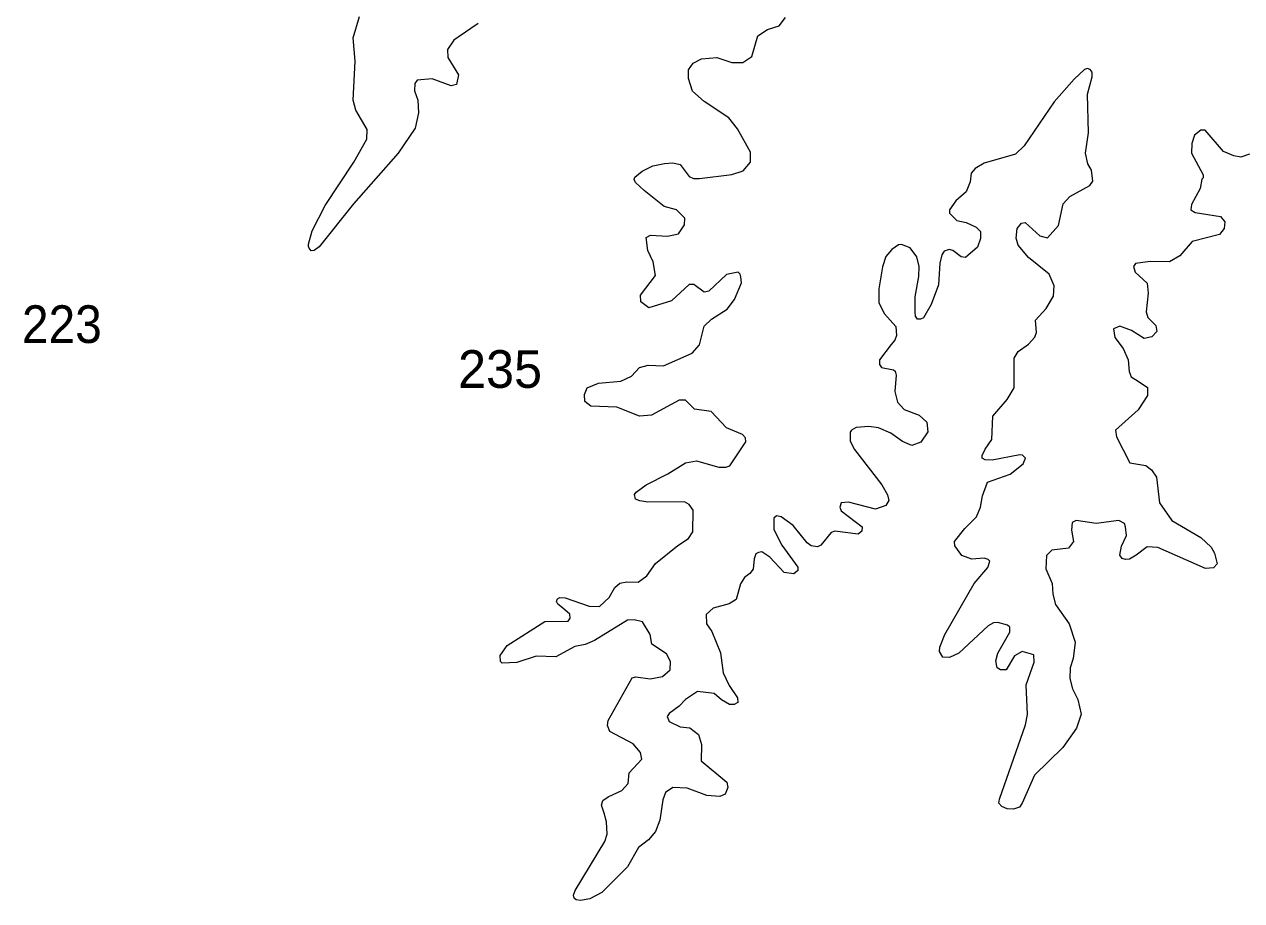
# Model space of a CAD drawing. Extents: x 499.9 to 555.3, y 9281.5 to 9336.8.
# Drawn here: x 512.89 to 518.06, y 9302.13 to 9305.85 of the extents above; entities that cross this region are included whole.
import ezdxf

# ---------------------------------------------------------------- set-up
doc = ezdxf.new("R2010")
doc.units = 0
doc.header["$LTSCALE"] = 0.064
doc.layers.add('2', color=7, linetype='Continuous', lineweight=13)
doc.layers.add('21', color=7, linetype='Continuous')

msp = doc.modelspace()

# ---------------------------------------------------------------- linework, layer by layer
at = {"layer": '2'}
for points in [[(514.8193, 9305.8589), (514.7874, 9305.8369), (514.7156, 9305.7877), (514.6882, 9305.7478), (514.69, 9305.7137), (514.7351, 9305.6398), (514.7267, 9305.5994), (514.7046, 9305.5935), (514.624, 9305.6231), (514.5599, 9305.6174), (514.5495, 9305.6034), (514.5478, 9305.5725), (514.562, 9305.5326), (514.5651, 9305.4786), (514.5516, 9305.4136), (514.4788, 9305.3076), (514.2894, 9305.0927), (514.1435, 9304.9091), (514.1218, 9304.8934), (514.109, 9304.8929), (514.1005, 9304.9034), (514.0978, 9304.9113), (514.0975, 9304.9206), (514.1143, 9304.9777), (514.1695, 9305.0845), (514.2911, 9305.2694), (514.3454, 9305.3672), (514.3469, 9305.4084), (514.2989, 9305.4895), (514.2885, 9305.5326), (514.2962, 9305.6981), (514.2884, 9305.7978), (514.3142, 9305.8875)], [(515.9078, 9304.6861), (515.9369, 9304.7561), (515.9342, 9304.7814), (515.9307, 9304.7937), (515.9224, 9304.8017), (515.873, 9304.7918), (515.798, 9304.7204), (515.779, 9304.7167), (515.735, 9304.7492), (515.7143, 9304.7495), (515.6404, 9304.6795), (515.5433, 9304.6499), (515.5099, 9304.676), (515.5086, 9304.7048), (515.5723, 9304.787), (515.5615, 9304.8451), (515.5393, 9304.8936), (515.5319, 9304.9484), (515.5504, 9304.9597), (515.6221, 9304.9551), (515.6696, 9304.9648), (515.6947, 9305.0036), (515.6966, 9305.0306), (515.6615, 9305.0668), (515.6088, 9305.0812), (515.5235, 9305.1493), (515.487, 9305.183), (515.4812, 9305.196), (515.4839, 9305.2058), (515.5155, 9305.2302), (515.561, 9305.2537), (515.6101, 9305.2636), (515.6454, 9305.2662), (515.6771, 9305.2589), (515.7146, 9305.2083), (515.7326, 9305.2), (515.7581, 9305.2001), (515.8966, 9305.2162), (515.9435, 9305.232), (515.9753, 9305.2693), (515.9752, 9305.3111), (515.9201, 9305.411), (515.883, 9305.4577), (515.778, 9305.5267), (515.729, 9305.571), (515.7114, 9305.625), (515.7118, 9305.6619), (515.7311, 9305.6904), (515.7667, 9305.7083), (515.832, 9305.714), (515.8959, 9305.6919), (515.943, 9305.6932), (515.9802, 9305.7178), (516.006, 9305.8062), (516.0481, 9305.833), (516.0975, 9305.8478), (516.1235, 9305.8836)], [(516.9596, 9304.0121), (516.959, 9304.0232), (516.9719, 9304.0493), (517, 9304.0907), (517.0042, 9304.1899), (517.0655, 9304.261), (517.0956, 9304.3104), (517.0951, 9304.4359), (517.112, 9304.4645), (517.1562, 9304.4966), (517.182, 9304.5258), (517.1895, 9304.5459), (517.1856, 9304.5973), (517.231, 9304.6478), (517.2615, 9304.7005), (517.2643, 9304.7432), (517.2434, 9304.7938), (517.1564, 9304.8642), (517.1123, 9304.9162), (517.104, 9304.9465), (517.1071, 9304.9875), (517.1257, 9305.0099), (517.142, 9305.0133), (517.2037, 9304.9556), (517.2371, 9304.9481), (517.2837, 9305.0005), (517.3025, 9305.0916), (517.3316, 9305.1234), (517.4157, 9305.1704), (517.4295, 9305.1883), (517.4239, 9305.2352), (517.408, 9305.2622), (517.3983, 9305.3073), (517.411, 9305.3934), (517.4063, 9305.5581), (517.4263, 9305.632), (517.4264, 9305.6514), (517.418, 9305.6623), (517.4063, 9305.6671), (517.3937, 9305.6628), (517.35, 9305.6213), (517.2651, 9305.5252), (517.1377, 9305.3391), (517.1004, 9305.3032), (516.967, 9305.2642), (516.9295, 9305.2418), (516.9123, 9305.2218), (516.908, 9305.1856), (516.8912, 9305.1425), (516.8472, 9305.1054), (516.8196, 9305.0669), (516.8203, 9305.0525), (516.8519, 9305.0216), (516.8914, 9305.0124), (516.9334, 9304.993), (516.9523, 9304.9739), (516.9524, 9304.9447), (516.9392, 9304.9084), (516.8888, 9304.8646), (516.8699, 9304.8676), (516.8342, 9304.8944), (516.8183, 9304.8974), (516.7975, 9304.8915), (516.7873, 9304.8752), (516.7793, 9304.8395), (516.7737, 9304.7479), (516.7428, 9304.6644), (516.7104, 9304.6083), (516.6974, 9304.6017), (516.6851, 9304.6025), (516.6765, 9304.6144), (516.6741, 9304.6325), (516.674, 9304.6968), (516.6899, 9304.7839), (516.6915, 9304.826), (516.6819, 9304.8672), (516.6533, 9304.9046), (516.616, 9304.9195), (516.6037, 9304.9184), (516.5755, 9304.8975), (516.5505, 9304.8679), (516.5357, 9304.8244), (516.5203, 9304.7307), (516.5195, 9304.6721), (516.5448, 9304.6245), (516.5925, 9304.5703), (516.5959, 9304.5332), (516.5881, 9304.5127), (516.5727, 9304.4951), (516.5236, 9304.4288), (516.523, 9304.4089), (516.5313, 9304.3975), (516.5828, 9304.3872), (516.5893, 9304.381), (516.5937, 9304.3643)], [(518.0944, 9305.303), (518.0571, 9305.2908), (518.0278, 9305.2959), (517.9839, 9305.3148), (517.9058, 9305.405), (517.887, 9305.405), (517.8604, 9305.3834), (517.8489, 9305.3487), (517.8474, 9305.3067), (517.8974, 9305.2151), (517.898, 9305.2029), (517.8918, 9305.1975), (517.8851, 9305.157), (517.8479, 9305.0887), (517.8458, 9305.0671), (517.8638, 9305.055), (517.9709, 9305.039), (517.99, 9305.0162), (517.9866, 9304.9868), (517.9673, 9304.9619), (517.8504, 9304.9324), (517.7982, 9304.8712), (517.7548, 9304.8454), (517.672, 9304.8467), (517.6103, 9304.839), (517.6024, 9304.8264), (517.6088, 9304.8025), (517.6422, 9304.7706), (517.66, 9304.7553), (517.6639, 9304.7131), (517.6548, 9304.6336), (517.6624, 9304.6094), (517.6965, 9304.5752), (517.7001, 9304.5491), (517.6798, 9304.527), (517.6473, 9304.5207), (517.5939, 9304.5537), (517.5434, 9304.5722), (517.5167, 9304.5614), (517.5227, 9304.5238), (517.5582, 9304.4771), (517.5793, 9304.4289), (517.5832, 9304.3805), (517.5922, 9304.3572), (517.6211, 9304.3389), (517.6605, 9304.3117)], [(515.727, 9304.457), (515.7586, 9304.4935), (515.7787, 9304.5718), (515.8096, 9304.6025), (515.8756, 9304.6452), (515.9078, 9304.6861)], [(515.3641, 9302.4673), (515.3531, 9302.5031), (515.3428, 9302.5373), (515.3477, 9302.5568), (515.3701, 9302.5734), (515.4291, 9302.5991), (515.4562, 9302.6298), (515.4604, 9302.6747), (515.5135, 9302.7323), (515.5084, 9302.7607), (515.4772, 9302.7982), (515.3773, 9302.8507), (515.3678, 9302.8756), (515.3708, 9302.897), (515.4732, 9303.0785), (515.4883, 9303.0831), (515.5489, 9303.0738), (515.6012, 9303.0841), (515.6345, 9303.1121), (515.6361, 9303.1485), (515.6182, 9303.1805), (515.5558, 9303.2215), (515.5486, 9303.2631), (515.5167, 9303.3169), (515.4813, 9303.3251), (515.4528, 9303.324), (515.3133, 9303.2377), (515.2727, 9303.2205), (515.2289, 9303.2112), (515.1478, 9303.1678), (515.065, 9303.1705), (514.983, 9303.144), (514.9204, 9303.1409), (514.9135, 9303.1485), (514.9124, 9303.1732), (514.9424, 9303.2164), (515.1017, 9303.3173), (515.2012, 9303.3192), (515.2094, 9303.3321), (515.2083, 9303.349), (515.1773, 9303.3759), (515.1574, 9303.3912), (515.1511, 9303.4031), (515.1552, 9303.4141), (515.1659, 9303.4201), (515.1883, 9303.4186), (515.2903, 9303.3828), (515.3344, 9303.3813), (515.3752, 9303.4191), (515.3986, 9303.4626), (515.4206, 9303.4802), (515.4503, 9303.4857), (515.4978, 9303.4847), (515.5346, 9303.5118), (515.5712, 9303.5636), (515.666, 9303.6413), (515.7114, 9303.6699), (515.7302, 9303.6983), (515.7317, 9303.7907), (515.7142, 9303.8147), (515.6944, 9303.8264), (515.5394, 9303.8251), (515.505, 9303.83), (515.4863, 9303.838), (515.4826, 9303.8571), (515.4903, 9303.8671), (515.5316, 9303.8989), (515.6236, 9303.9449), (515.6993, 9303.9921), (515.7462, 9303.9997), (515.841, 9303.9732), (515.8711, 9303.9727), (515.8874, 9303.9784), (515.9559, 9304.0812), (515.9544, 9304.0984), (515.9416, 9304.1115), (515.8731, 9304.1401), (515.8087, 9304.2094), (515.7373, 9304.2197), (515.6992, 9304.2577), (515.6718, 9304.2586), (515.5552, 9304.1944), (515.5044, 9304.1896), (515.408, 9304.2276), (515.2969, 9304.233), (515.2723, 9304.2523), (515.2709, 9304.2826), (515.2815, 9304.3103), (515.3293, 9304.3309), (515.4247, 9304.3391), (515.4692, 9304.3598), (515.5044, 9304.3967), (515.5401, 9304.4073), (515.6061, 9304.4045), (515.727, 9304.457)], [(516.5937, 9304.3643), (516.5882, 9304.2952), (516.5996, 9304.25), (516.6281, 9304.2182), (516.6909, 9304.1944), (516.7236, 9304.1651)], [(517.6605, 9304.3117), (517.6618, 9304.2785), (517.622, 9304.2176), (517.5259, 9304.1308), (517.5292, 9304.1028), (517.5859, 9303.9912)], [(516.7236, 9304.1651), (516.7289, 9304.1242), (516.6989, 9304.079), (516.6605, 9304.0656), (516.6201, 9304.082), (516.5713, 9304.1172), (516.5189, 9304.1401), (516.4783, 9304.1462), (516.424, 9304.1417), (516.4043, 9304.1308), (516.3991, 9304.1216), (516.399, 9304.0844), (516.4163, 9304.0478), (516.5328, 9303.899), (516.5574, 9303.8558), (516.5624, 9303.8312), (516.5502, 9303.8111), (516.5064, 9303.7948), (516.3915, 9303.8249), (516.3605, 9303.8225), (516.3545, 9303.8037), (516.3609, 9303.7875), (516.4492, 9303.7197), (516.4477, 9303.7009), (516.4327, 9303.6886), (516.3335, 9303.701), (516.3173, 9303.6961), (516.2743, 9303.6419), (516.2592, 9303.6344), (516.2323, 9303.6386), (516.2161, 9303.6517), (516.1557, 9303.7256), (516.105, 9303.7623), (516.0854, 9303.7671), (516.0747, 9303.7568), (516.0748, 9303.7089), (516.1088, 9303.6425), (516.1763, 9303.5482), (516.1768, 9303.5348), (516.1592, 9303.5196), (516.1183, 9303.5253), (516.0574, 9303.5913), (516.0238, 9303.6141), (516.0086, 9303.6104), (515.9972, 9303.6047), (515.9908, 9303.5844), (515.9865, 9303.5407), (515.9727, 9303.5215), (515.9503, 9303.5045), (515.9331, 9303.4776), (515.9146, 9303.4113), (515.8847, 9303.3921), (515.8164, 9303.3742), (515.7863, 9303.3482), (515.788, 9303.3077), (515.8117, 9303.275), (515.8479, 9303.1842), (515.8596, 9303.1), (515.8841, 9303.0465), (515.9207, 9302.9931), (515.9209, 9302.9736), (515.9054, 9302.9657), (515.8863, 9302.9657), (515.8514, 9302.9846), (515.8209, 9303.0114), (515.7495, 9303.0209), (515.6991, 9302.9866), (515.6728, 9302.9575), (515.6292, 9302.9276), (515.621, 9302.9145), (515.6305, 9302.8927), (515.6763, 9302.8701), (515.7182, 9302.8661), (515.7549, 9302.8371), (515.7668, 9302.7951), (515.7657, 9302.7253), (515.8746, 9302.6348), (515.8796, 9302.6122), (515.8675, 9302.5846), (515.8451, 9302.574), (515.7894, 9302.5785), (515.7056, 9302.6103), (515.6454, 9302.6132), (515.6147, 9302.5913), (515.603, 9302.5596), (515.5903, 9302.4744), (515.572, 9302.4263), (515.5424, 9302.3909), (515.4997, 9302.3573), (515.4522, 9302.2749), (515.3441, 9302.167), (515.293, 9302.139), (515.2529, 9302.1318), (515.2353, 9302.136), (515.2263, 9302.1426)], [(517.5859, 9303.9912), (517.6539, 9303.98), (517.6788, 9303.9626), (517.6996, 9303.9314), (517.7116, 9303.822), (517.765, 9303.7465), (517.8878, 9303.6741), (517.9318, 9303.6336), (517.9456, 9303.6079), (517.9565, 9303.5625), (517.9417, 9303.5464), (517.9077, 9303.5435), (517.7046, 9303.6319), (517.6596, 9303.6353), (517.6124, 9303.6002), (517.5853, 9303.5826), (517.5671, 9303.5807), (517.5539, 9303.5852), (517.5432, 9303.6002), (517.551, 9303.6381), (517.5715, 9303.6836), (517.5681, 9303.7205), (517.5629, 9303.7344), (517.5398, 9303.7466), (517.4429, 9303.7342), (517.3588, 9303.7467), (517.3414, 9303.7386), (517.3379, 9303.7055), (517.3471, 9303.6583), (517.3257, 9303.6293), (517.2546, 9303.6204), (517.2328, 9303.5979), (517.23, 9303.541), (517.2566, 9303.4787), (517.2585, 9303.4342), (517.271, 9303.3905), (517.3284, 9303.3085), (517.3534, 9303.2302), (517.3457, 9303.1612), (517.3333, 9303.1206), (517.3315, 9303.076), (517.3424, 9303.0315), (517.3658, 9302.9861), (517.3788, 9302.9234), (517.3599, 9302.8653), (517.3013, 9302.7825), (517.1819, 9302.6646), (517.1289, 9302.5453), (517.1172, 9302.5289), (517.0916, 9302.5202), (517.0654, 9302.5215), (517.0431, 9302.5321), (517.0297, 9302.5466), (517.0321, 9302.5627), (517.1437, 9302.8787), (517.1515, 9302.9233), (517.1454, 9303.049), (517.1799, 9303.1445), (517.1786, 9303.1763), (517.1294, 9303.1905), (517.0961, 9303.1721), (517.0606, 9303.1129), (517.0362, 9303.112), (517.0228, 9303.1215), (517.0166, 9303.15), (517.0257, 9303.1828), (517.0768, 9303.2725), (517.0764, 9303.2931), (517.0672, 9303.3015), (517.0252, 9303.3139), (517.0068, 9303.3122), (516.9845, 9303.2996), (516.86, 9303.1832), (516.8206, 9303.1651), (516.792, 9303.1661), (516.7782, 9303.1896), (516.7788, 9303.2085), (516.7999, 9303.2631), (516.9253, 9303.4795), (516.9838, 9303.5474), (516.9918, 9303.5734), (516.9849, 9303.5811), (516.9679, 9303.5868), (516.9153, 9303.5829), (516.8729, 9303.598), (516.8431, 9303.6388), (516.8421, 9303.6575), (516.8861, 9303.7129), (516.9353, 9303.762), (516.9523, 9303.8034), (516.9606, 9303.8519), (516.9811, 9303.9101), (517.0783, 9303.9443), (517.1334, 9303.9869), (517.1427, 9304.0117)], [(517.1427, 9304.0117), (517.1305, 9304.0242), (517.119, 9304.0252), (517.0012, 9304.0035), (516.9722, 9304.0043), (516.9596, 9304.0121)], [(515.2263, 9302.1426), (515.2237, 9302.1549), (515.2312, 9302.175), (515.357, 9302.3829), (515.3671, 9302.414), (515.3641, 9302.4673)]]:
    msp.add_lwpolyline(points, dxfattribs=at)

# ---------------------------------------------------------------- texts
at = {"layer": '21', "width": 0.95}
msp.add_text('223', height=0.16, dxfattribs=at).set_placement((512.8812, 9304.501))
at = {"layer": '21'}
msp.add_text('235', height=0.16, dxfattribs=at).set_placement((514.7331, 9304.3104))

doc.saveas('drawing.dxf')
